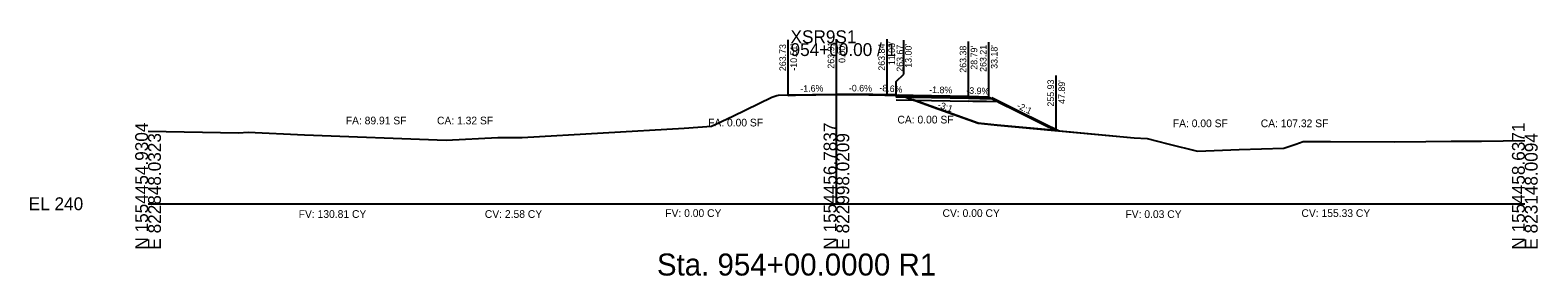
# Model space of a CAD drawing. Extents: x -26 to 823017, y -16 to 1558356.
# Drawn here: x -25.7 to 302.8, y 1984.3 to 2037.8 of the extents above; entities that cross this region are included whole.
import ezdxf

# ---------------------------------------------------------------- set-up
doc = ezdxf.new("R2010")
doc.units = 0
for name, color, linetype in [('ASPHALT_19MM1', 7, 'Continuous'), ('CONST_DCH', 7, 'Continuous'), ('CONST_LV3', 7, 'Continuous'), ('Draft_XS_Grid', 7, 'Continuous'), ('Draft_XS_Text', 7, 'Continuous'), ('DTM_CORRIDOR', 7, 'Continuous'), ('DTM_P_FINISHED_GRADE2', 7, 'Continuous'), ('DTM_TEMP_DROP', 7, 'Continuous'), ('DTM_X_GROUND', 7, 'Continuous'), ('PROFILES_DCH_2', 7, 'Continuous'), ('XS_CELL', 7, 'Continuous'), ('XS_M_SHAPES_EARTHWORK', 7, 'Continuous'), ('XS_P_ASPHALT', 7, 'Continuous'), ('XS_P_DR_GRAVEL', 7, 'Continuous'), ('XS_P_GROUND', 7, 'Continuous'), ('XS_P_SHOULDER', 7, 'Continuous'), ('XS_P_SUBGRADE_GRANULAR', 7, 'Continuous'), ('XS_P_SUBGRADE_LEVELING', 7, 'Continuous'), ('XS_P_SUBGRADE_MILLING', 7, 'Continuous'), ('XS_P_SUBGRADE_UNDERCUT', 7, 'Continuous'), ('XS_P_TX_CLEARZONE', 7, 'Continuous'), ('XS_P_TX_FS_BS', 7, 'Continuous'), ('XS_SHEET_EW_TX_AREA', 7, 'Continuous'), ('XS_SHEET_EW_TX_VOLUME', 7, 'Continuous')]:
    doc.layers.add(name, color=color, linetype=linetype)

msp = doc.modelspace()

# ---------------------------------------------------------------- linework, layer by layer
at = {"layer": 'ASPHALT_19MM1'}
for points in [[(163, 2023.5), (163, 2023.29), (166.69, 2023.23), (166.69, 2023.43), (163, 2023.5)], [(166.69, 2023.43), (166.69, 2023.23), (178.79, 2023.01), (178.79, 2023.22), (166.69, 2023.43)]]:
    msp.add_lwpolyline(points, dxfattribs=at)
at = {"layer": 'CONST_DCH'}
for points in [[(163, 2023.67), (163, 2023.5), (166.69, 2023.43), (166.69, 2023.6), (163, 2023.67)], [(166.69, 2023.6), (166.69, 2023.43), (178.79, 2023.22), (178.79, 2023.38), (166.69, 2023.6)]]:
    msp.add_lwpolyline(points, dxfattribs=at)
at = {"layer": 'CONST_LV3'}
for points in [[(150, 2023.91), (164, 2023.63)], [(161.06, 2023.84), (161.06, 2023.84), (162.91, 2023.83), (162.91, 2023.82), (162.91, 2023.82), (162.91, 2023.82), (162.91, 2023.82), (162.91, 2023.82), (162.91, 2023.82), (162.91, 2023.82), (162.91, 2023.81), (162.91, 2023.81), (162.91, 2023.81), (162.91, 2023.81), (162.91, 2023.81), (162.91, 2023.81), (162.91, 2023.81), (162.91, 2023.81), (162.91, 2023.81), (162.94, 2023.63), (162.95, 2023.64), (162.95, 2023.64), (162.95, 2023.64), (162.95, 2023.64), (162.96, 2023.64), (162.98, 2023.65), (162.99, 2023.66), (162.99, 2023.66), (162.99, 2023.66), (162.99, 2023.66), (163, 2023.67), (163, 2023.67), (166.69, 2023.6), (166.69, 2023.6), (175.22, 2023.45), (178.79, 2023.38), (180.98, 2023.3), (183.18, 2023.21), (187.23, 2021.21), (187.27, 2021.18), (195.14, 2017.29), (197.52, 2016.11), (197.89, 2015.93), (197.91, 2015.93), (214.84, 2014.39), (217.68, 2014.21), (222.24, 2013.06), (228.7, 2011.49), (237.72, 2011.86), (247.47, 2012.11), (250.13, 2013.01), (251.7, 2013.54), (257.63, 2013.54), (271.6, 2013.53), (278.41, 2013.58), (283.98, 2013.61), (287.78, 2013.63), (290.56, 2013.65), (300, 2013.79)], [(0, 2015.85), (19.69, 2015.43), (21.82, 2015.57), (34.12, 2015.04), (64.98, 2013.89), (76.25, 2014.43), (81.49, 2014.47), (116.82, 2016.44), (122.81, 2016.9), (127.45, 2019.1), (135.93, 2023.21), (137.01, 2023.57), (137.41, 2023.7), (139.49, 2023.73), (139.49, 2023.73)], [(163.36, 2023.65), (163.36, 2023.65), (164, 2023.63)], [(183.84, 2023.16), (189.2, 2020.5), (195.14, 2017.56), (198.55, 2015.87)]]:
    msp.add_lwpolyline(points, dxfattribs=at)
at = {"layer": 'DTM_P_FINISHED_GRADE2'}
msp.add_lwpolyline([(139.49, 2023.73), (150, 2023.91), (161.06, 2023.84)], dxfattribs=at)
at = {"layer": 'DTM_X_GROUND'}
for points in [[(0, 2015.85), (19.69, 2015.43), (21.82, 2015.57), (34.12, 2015.04), (64.98, 2013.89), (76.25, 2014.43), (81.49, 2014.47), (116.82, 2016.44), (122.81, 2016.9), (127.45, 2019.1), (135.93, 2023.21), (137.01, 2023.57), (137.41, 2023.7), (141.08, 2023.76), (150.15, 2023.91), (157.93, 2023.77), (163, 2023.67), (164.37, 2023.38), (164.9, 2023.27), (171.07, 2021.07), (180.87, 2017.59), (185.02, 2017.11), (214.84, 2014.39), (217.68, 2014.21), (222.24, 2013.06), (228.7, 2011.49), (237.72, 2011.86), (247.47, 2012.11), (250.13, 2013.01), (251.7, 2013.54), (257.63, 2013.54), (271.6, 2013.53), (278.41, 2013.58), (283.98, 2013.61), (287.78, 2013.63), (290.56, 2013.65), (300, 2013.79)], [(0, 2015.85), (19.69, 2015.43), (21.82, 2015.57), (34.12, 2015.04), (64.98, 2013.89), (76.25, 2014.43), (81.49, 2014.47), (116.82, 2016.44), (122.81, 2016.9), (127.45, 2019.1), (135.93, 2023.21), (137.01, 2023.57), (137.41, 2023.7), (141.08, 2023.76), (150.15, 2023.91), (157.87, 2023.85), (157.93, 2023.85), (162.91, 2023.83), (162.91, 2023.82), (162.91, 2023.82), (162.91, 2023.82), (162.91, 2023.82), (162.91, 2023.82), (162.91, 2023.82), (162.91, 2023.82), (162.91, 2023.81), (162.91, 2023.81), (162.91, 2023.81), (162.91, 2023.81), (162.91, 2023.81), (162.91, 2023.81), (162.91, 2023.81), (162.91, 2023.81), (162.91, 2023.81), (162.94, 2023.63), (162.95, 2023.64), (162.95, 2023.64), (162.95, 2023.64), (162.95, 2023.64), (162.96, 2023.64), (162.98, 2023.65), (162.99, 2023.66), (162.99, 2023.66), (162.99, 2023.66), (162.99, 2023.66), (163, 2023.67), (163, 2023.67), (166.69, 2023.6), (166.69, 2023.6), (175.22, 2023.45), (178.79, 2023.38), (180.98, 2023.3), (183.18, 2023.21), (187.23, 2021.21), (187.27, 2021.18), (195.14, 2017.29), (197.52, 2016.11), (197.89, 2015.93), (197.91, 2015.93), (214.84, 2014.39), (217.68, 2014.21), (222.24, 2013.06), (228.7, 2011.49), (237.72, 2011.86), (247.47, 2012.11), (250.13, 2013.01), (251.7, 2013.54), (257.63, 2013.54), (271.6, 2013.53), (278.41, 2013.58), (283.98, 2013.61), (287.78, 2013.63), (290.56, 2013.65), (300, 2013.79)], [(0, 2015.85), (19.69, 2015.43), (21.82, 2015.57), (34.12, 2015.04), (64.98, 2013.89), (76.25, 2014.43), (81.49, 2014.47), (116.82, 2016.44), (122.81, 2016.9), (127.45, 2019.1), (135.93, 2023.21), (137.01, 2023.57), (137.41, 2023.7), (139.49, 2023.73), (139.49, 2023.73), (150, 2023.91), (150, 2023.91), (150, 2023.91), (150, 2023.91), (150, 2023.91), (150, 2023.91), (150, 2023.91), (150, 2023.91), (161.06, 2023.84), (161.06, 2023.84), (161.06, 2023.84), (162.91, 2023.83), (162.91, 2023.82), (162.91, 2023.82), (162.91, 2023.82), (162.91, 2023.82), (162.91, 2023.82), (162.91, 2023.82), (162.91, 2023.82), (162.91, 2023.81), (162.91, 2023.81), (162.91, 2023.81), (162.91, 2023.81), (162.91, 2023.81), (162.91, 2023.81), (162.91, 2023.81), (162.91, 2023.81), (162.91, 2023.81), (162.94, 2023.63), (162.95, 2023.64), (162.95, 2023.64), (162.95, 2023.64), (162.95, 2023.64), (162.96, 2023.64), (162.98, 2023.65), (162.99, 2023.66), (162.99, 2023.66), (162.99, 2023.66), (162.99, 2023.66), (163, 2023.67), (163, 2023.67), (166.69, 2023.6), (166.69, 2023.6), (175.22, 2023.45), (178.79, 2023.38), (180.98, 2023.3), (183.18, 2023.21), (187.23, 2021.21), (187.27, 2021.18), (195.14, 2017.29), (197.52, 2016.11), (197.89, 2015.93), (197.91, 2015.93), (214.84, 2014.39), (217.68, 2014.21), (222.24, 2013.06), (228.7, 2011.49), (237.72, 2011.86), (247.47, 2012.11), (250.13, 2013.01), (251.7, 2013.54), (257.63, 2013.54), (271.6, 2013.53), (278.41, 2013.58), (283.98, 2013.61), (287.78, 2013.63), (290.56, 2013.65), (300, 2013.79)]]:
    msp.add_lwpolyline(points, dxfattribs=at)
at = {"layer": 'XS_CELL'}
for p, q in [((150, 2000), (150, 2035)), ((0, 2000), (150, 2000)), ((150, 2000), (300, 2000))]:
    msp.add_line(p, q, dxfattribs=at)
at = {"layer": 'XS_M_SHAPES_EARTHWORK'}
msp.add_lwpolyline([(160.65, 2023.71), (161.06, 2023.71), (161.06, 2023.71)], close=True, dxfattribs=at)
at = {"layer": 'XS_P_ASPHALT'}
msp.add_lwpolyline([(139.49, 2023.73), (150, 2023.91), (150, 2023.91), (161.06, 2023.84), (161.06, 2023.84), (161.06, 2023.71), (161.06, 2023.71), (150, 2023.78), (150, 2023.78), (139.49, 2023.61), (139.49, 2023.73)], dxfattribs=at)
at = {"layer": 'XS_P_DR_GRAVEL'}
msp.add_lwpolyline([(180.98, 2023.3), (178.79, 2023.38), (178.79, 2023.22), (178.79, 2023.01), (181.23, 2022.96), (183.76, 2022.92), (183.42, 2023.09), (183.18, 2023.21), (180.98, 2023.3)], dxfattribs=at)
at = {"layer": 'XS_P_GROUND'}
for points in [[(163.87, 2023.48), (163.36, 2023.65), (163.36, 2023.65)], [(163.87, 2023.48), (163.87, 2023.48), (164.37, 2023.38), (164.37, 2023.38), (164.9, 2023.27), (171.07, 2021.07), (171.07, 2021.07), (180.87, 2017.59), (180.87, 2017.59), (185.02, 2017.11), (185.02, 2017.11), (198.55, 2015.87), (198.55, 2015.87)], [(163.87, 2023.48), (163.87, 2023.48), (164.37, 2023.38), (164.37, 2023.38), (164.9, 2023.27), (171.07, 2021.07), (171.07, 2021.07), (180.87, 2017.59), (180.87, 2017.59), (185.02, 2017.11), (185.02, 2017.11), (198.55, 2015.87), (198.55, 2015.87)], [(183.18, 2023.21), (195.14, 2017.29), (197.89, 2015.93)]]:
    msp.add_lwpolyline(points, dxfattribs=at)
at = {"layer": 'XS_P_SHOULDER'}
msp.add_lwpolyline([(178.79, 2023.38), (183.18, 2023.21)], dxfattribs=at)
at = {"layer": 'XS_P_SUBGRADE_GRANULAR'}
for points in [[(163, 2022.63), (166.69, 2022.56), (178.79, 2022.34)], [(185.2, 2022.21), (182.73, 2022.26), (180.81, 2022.3), (179.71, 2022.32), (178.79, 2022.34)]]:
    msp.add_lwpolyline(points, dxfattribs=at)
at = {"layer": 'XS_P_SUBGRADE_LEVELING'}
msp.add_lwpolyline([(139.49, 2023.61), (141.08, 2023.64), (141.08, 2023.64), (150, 2023.78), (150, 2023.78), (150.15, 2023.78), (150.15, 2023.78), (157.87, 2023.73), (157.87, 2023.73), (157.93, 2023.73), (161.06, 2023.71)], dxfattribs=at)
msp.add_lwpolyline([(139.49, 2023.61), (141.08, 2023.64), (141.08, 2023.64), (150, 2023.78), (150, 2023.78), (150.15, 2023.78), (150.15, 2023.78), (157.87, 2023.73), (157.87, 2023.73), (157.93, 2023.73), (161.06, 2023.71)], dxfattribs=at)
at = {"layer": 'XS_P_SUBGRADE_MILLING'}
msp.add_lwpolyline([(157.93, 2023.85), (161.06, 2023.84), (161.06, 2023.71), (157.93, 2023.73), (157.87, 2023.73), (157.87, 2023.73), (150.15, 2023.78), (150.15, 2023.78), (150, 2023.78), (150, 2023.78), (141.08, 2023.64), (141.08, 2023.64), (139.49, 2023.61), (139.49, 2023.73), (141.08, 2023.76), (141.08, 2023.76), (150, 2023.91), (150, 2023.91), (150.15, 2023.91), (150.15, 2023.91), (157.87, 2023.85), (157.87, 2023.85), (157.93, 2023.85)], dxfattribs=at)
at = {"layer": 'XS_P_SUBGRADE_UNDERCUT'}
for p, q in [((163.68, 2023.52), (163, 2023.67)), ((163, 2023.67), (166.69, 2023.6)), ((164.9, 2023.27), (163.68, 2023.52)), ((180.87, 2017.59), (164.9, 2023.27)), ((166.69, 2023.6), (175.22, 2023.45)), ((175.22, 2023.45), (178.79, 2023.38)), ((178.79, 2023.38), (183.18, 2023.21)), ((183.18, 2023.21), (197.89, 2015.93)), ((185.02, 2017.11), (180.87, 2017.59)), ((197.89, 2015.93), (185.02, 2017.11))]:
    msp.add_line(p, q, dxfattribs=at)
at = {"layer": 'XS_P_TX_CLEARZONE'}
for p, q in [((139.49, 2023.73), (139.49, 2035.73)), ((150, 2023.91), (150, 2035.91)), ((161.06, 2023.84), (161.06, 2035.84)), ((164.72, 2028.26), (164.72, 2035.67)), ((178.79, 2023.38), (178.79, 2035.38)), ((183.18, 2023.21), (183.18, 2035.21)), ((163, 2026.68), (164.72, 2028.26)), ((197.89, 2015.93), (197.89, 2027.93)), ((163, 2023.67), (163, 2026.68))]:
    msp.add_line(p, q, dxfattribs=at)

# ---------------------------------------------------------------- texts
at = {"layer": 'CONST_DCH'}
for p in [(197.81, 2015.81), (198.47, 2015.75)]:
    msp.add_text('X', height=0.24, dxfattribs=at).set_placement(p)
at = {"layer": 'Draft_XS_Grid'}
msp.add_text('-', height=0.0001, dxfattribs=at).set_placement((0, 2000))
at = {"layer": 'Draft_XS_Text'}
msp.add_text('Sta. 954+00.0000 R1', height=4.8, dxfattribs=at).set_placement((110.88, 1984.35))
at = {"layer": 'DTM_CORRIDOR'}
for p in [(162.92, 2023.55), (166.61, 2023.48), (178.71, 2023.26)]:
    msp.add_text('X', height=0.24, dxfattribs=at).set_placement(p)
at = {"layer": 'DTM_TEMP_DROP'}
for p in [(139.41, 2023.61), (149.92, 2023.79), (160.98, 2023.72)]:
    msp.add_text('X', height=0.24, dxfattribs=at).set_placement(p)
at = {"layer": 'PROFILES_DCH_2'}
for p in [(163.28, 2023.53), (163.79, 2023.36), (198.47, 2015.75)]:
    msp.add_text('X', height=0.24, dxfattribs=at).set_placement(p)
at = {"layer": 'XS_CELL'}
for s, p in [('XSR9S1', (140, 2035)), ('954+00.00 / 1', (140, 2032.2)), ('EL 240', (-26, 1998.6))]:
    msp.add_text(s, height=2.8, dxfattribs=at).set_placement(p)
for s, p in [('N 1554454.9304', (0, 1990)), ('N 1554456.7837', (150, 1990)), ('N 1554458.6371', (300, 1990)), ('E 822848.0323', (2.8, 1990)), ('E 822998.0209', (152.8, 1990)), ('E 823148.0094', (302.8, 1990))]:
    msp.add_text(s, height=2.8, rotation=90, dxfattribs=at).set_placement(p)
at = {"layer": 'XS_P_ASPHALT'}
msp.add_text('X', height=0.24, dxfattribs=at).set_placement((197.81, 2015.81))
at = {"layer": 'XS_P_SHOULDER'}
msp.add_text('X', height=0.24, dxfattribs=at).set_placement((183.1, 2023.09))
at = {"layer": 'XS_P_TX_CLEARZONE'}
for s, p in [('263.73', (139.01, 2028.91)), ("-10.51'", (141.41, 2029)), ('263.91', (149.52, 2029.45)), ("0.00'", (151.92, 2030.69)), ('263.84', (160.58, 2029.01)), ("11.06'", (162.75, 2030.21)), ('263.67', (164.55, 2028.78)), ("13.00'", (166.39, 2029.64)), ('263.38', (178.31, 2028.56)), ("28.79'", (180.71, 2029.22)), ('263.21', (182.7, 2028.75)), ("33.18'", (185.1, 2029.41)), ('255.93', (197.41, 2021.18)), ("47.89'", (199.81, 2021.77))]:
    msp.add_text(s, height=1.44, rotation=90, dxfattribs=at).set_placement(p)
at = {"layer": 'XS_P_TX_FS_BS'}
for s, rotation, p in [('-1.6%', 0.9396, (142.14, 2024.38)), ('-0.6%', 359.6294, (152.71, 2024.49)), ('-8.6%', 355.058, (159.32, 2024.59)), ('-1.8%', 358.9685, (170.2, 2024.14)), ('-3.9%', 357.743, (178.27, 2024)), ('-3:1', 341.5651, (171.92, 2020.98)), ('-2:1', 333.6835, (189.17, 2020.91))]:
    msp.add_text(s, height=1.44, rotation=rotation, dxfattribs=at).set_placement(p)
at = {"layer": 'XS_SHEET_EW_TX_AREA'}
for s, p in [('FA: 89.91 SF', (43.08, 2017.3)), ('CA: 1.32 SF', (62.96, 2017.3)), ('FA: 0.00 SF', (122.03, 2016.85)), ('CA: 0.00 SF', (163.29, 2017.5)), ('FA: 0.00 SF', (223.3, 2016.69)), ('CA: 107.32 SF', (242.46, 2016.69))]:
    msp.add_text(s, height=1.68, dxfattribs=at).set_placement(p)
at = {"layer": 'XS_SHEET_EW_TX_VOLUME'}
for s, p in [('FV: 130.81 CY', (32.82, 1996.92)), ('CV: 2.58 CY', (73.39, 1996.92)), ('FV: 0.00 CY', (112.7, 1997.12)), ('CV: 0.00 CY', (173.12, 1997.12)), ('FV: 0.03 CY', (212.97, 1996.9)), ('CV: 155.33 CY', (251.33, 1997.12))]:
    msp.add_text(s, height=1.68, dxfattribs=at).set_placement(p)

doc.saveas('drawing.dxf')
